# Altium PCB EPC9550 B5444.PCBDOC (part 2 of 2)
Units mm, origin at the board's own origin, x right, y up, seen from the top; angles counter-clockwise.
Board outline 50 x 37 mm, 8 copper layers (Top Layer, Mid-Layer 1, Mid Layer 2 (Gnd), Mid-Layer 3 (Gnd), Mid-Layer 4 (54V), Mid Layer 5 (54V), Mid-Layer 6, Bottom Layer), stack 1.444 mm thick; 107 components, 61 nets, 523 pads, 597 vias.
Unrouted connection lines stored in the file: 17.
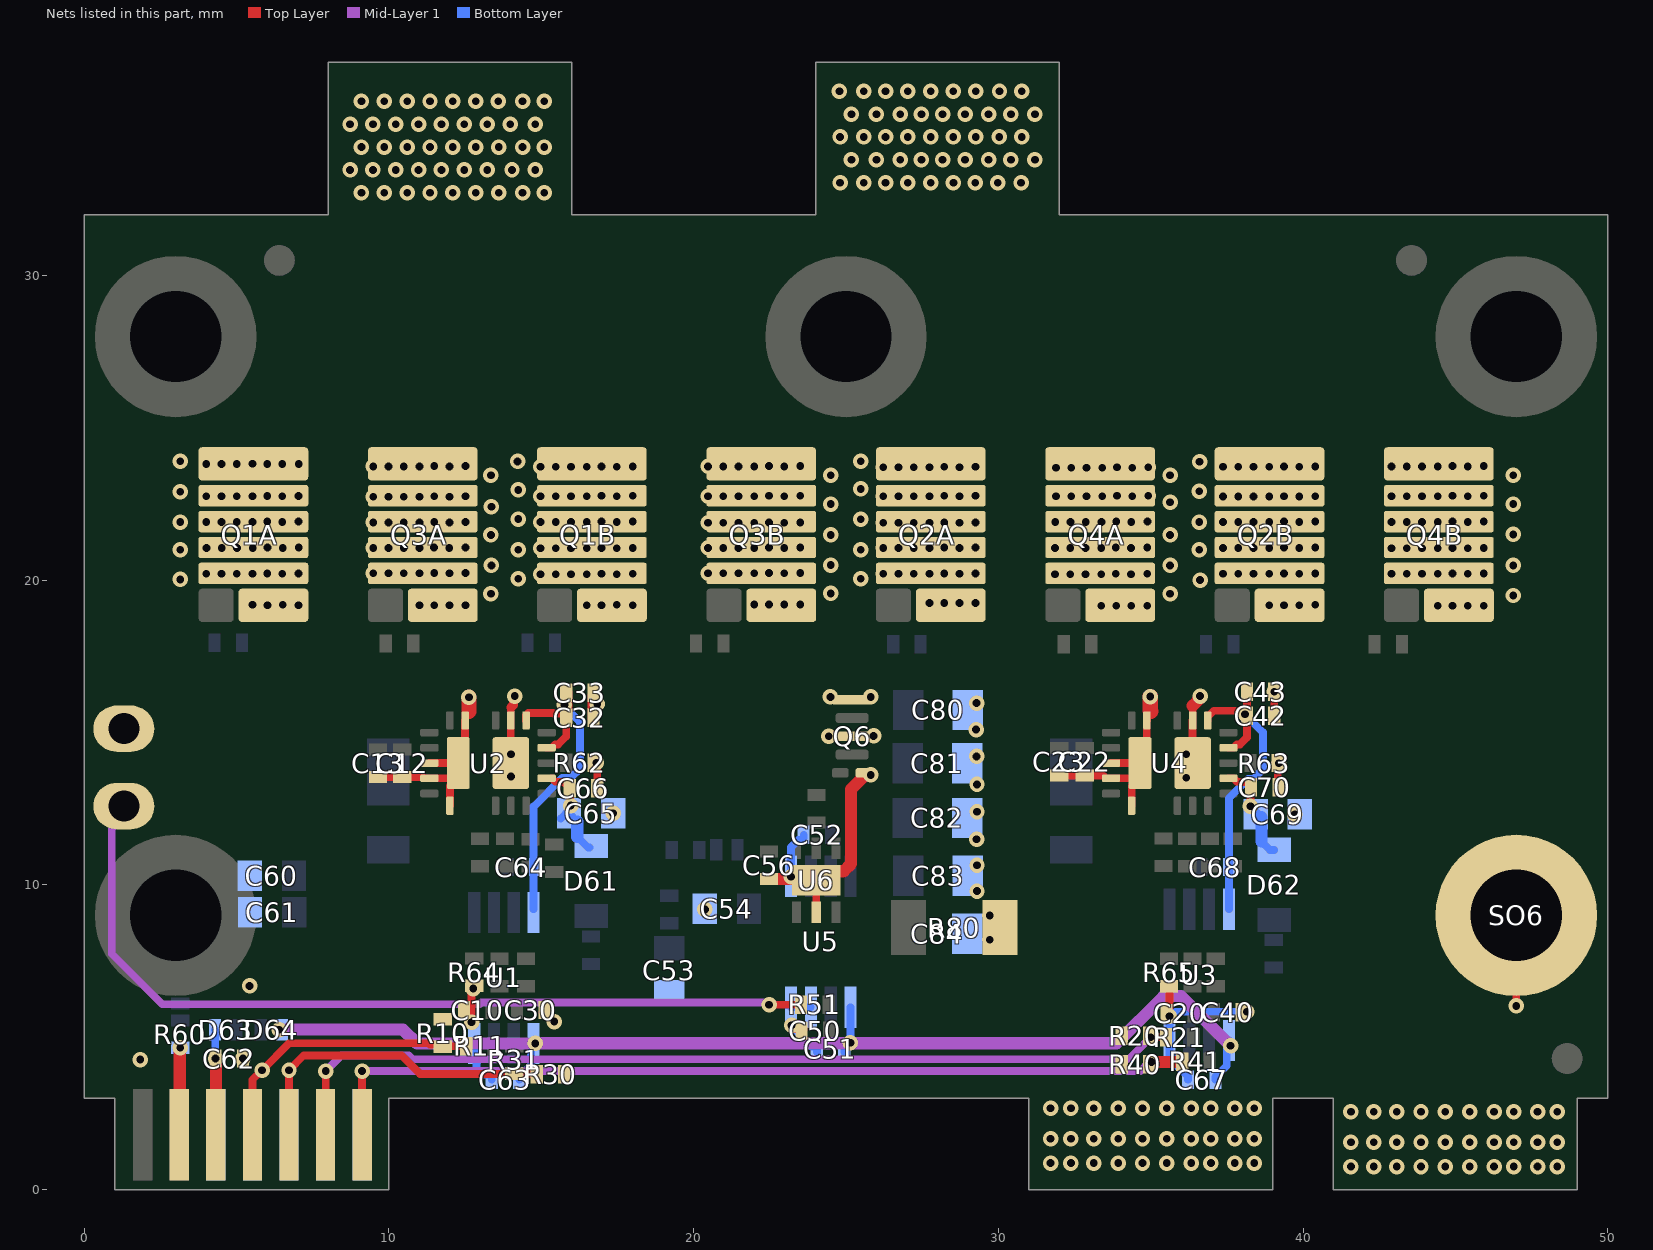
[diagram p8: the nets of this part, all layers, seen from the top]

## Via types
v1: diameter 0.508, hole 0.254, Top Layer to Bottom Layer, tented both sides, 565 vias
v2: diameter 0.508, hole 0.254, Top Layer to Bottom Layer, 32 vias

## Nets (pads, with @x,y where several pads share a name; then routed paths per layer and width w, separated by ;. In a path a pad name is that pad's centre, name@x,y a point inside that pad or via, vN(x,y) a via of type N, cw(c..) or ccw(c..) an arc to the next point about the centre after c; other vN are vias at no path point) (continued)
PRE_54V: C52.2 C54.1 C56.1 Q1A.3 Q1A.5 Q1A.7 Q1B.3 Q1B.5 Q1B.7 Q2A.3 Q2A.5 Q2A.7 Q2B.3 Q2B.5 Q2B.7 Q6.2 Q6.4 Q6.6 U5.5 U6.2 U6.EP | length 8.9
  Top Layer w0.254: v1@23.196,10.2 23.973,10.2 U6.EP@24.023,10.15 ; U6.2@24.023,9.1 U6.EP@24.023,10.15 ; U6.EP@24.057,10.183 U6.EP@24.023,10.15
  Top Layer w0.4: C56.1@22.474,10.2 v1@23.196,10.2 ; U6.EP@24.057,10.183 24.323,10.45 24.926,10.45 25.16,10.684 25.16,13.138 25.632,13.609 v1(25.811,13.609)
  Bottom Layer w0.254: C54.1@20.359,9.225 C54.1@20.368,9.216 ; U5.5@23.196,10.285 23.196,11.237 23.437,11.477 23.537,11.477 23.61,11.55 C52.2@23.61,11.65
  other v1: 31.715,0.87 32.384,0.87 33.132,0.87 33.932,0.87 34.732,0.87 35.532,0.87 36.332,0.87 36.978,0.87 37.757,0.87 38.401,0.87 31.715,1.67 32.384,1.67 33.132,1.67 33.932,1.67 34.732,1.67 35.532,1.67 36.332,1.67 36.978,1.67 37.757,1.67 38.401,1.67 31.715,2.67 32.384,2.67 33.132,2.67 33.932,2.67 34.732,2.67 35.532,2.67 36.332,2.67 36.978,2.67 37.757,2.67 38.401,2.67 20.37,9.195 23.196,10.27 24.438,14.88 25.905,14.89 24.489,16.17 25.811,16.17 36.623,20.007 3.15,20.028 14.242,20.054 25.487,20.054 14.974,20.197 15.474,20.197 15.974,20.197 16.491,20.197 17.474,20.197 4,20.211 4.5,20.211 5,20.211 5.517,20.211 6,20.225 6.5,20.211 7.026,20.225 16.974,20.211 18,20.211 26.224,20.211 26.724,20.211 27.224,20.211 27.741,20.211 28.224,20.225 28.724,20.211 29.25,20.225 37.374,20.211 37.874,20.211 38.374,20.211 38.891,20.211 39.374,20.225 39.874,20.211 40.4,20.225 3.15,21 14.242,21 25.487,21 36.594,21 26.224,21.884 26.724,21.884 27.224,21.884 27.741,21.884 28.224,21.897 28.724,21.884 29.25,21.897 3.15,21.911 4,21.911 4.5,21.911 5,21.911 5.517,21.911 6,21.925 6.5,21.911 7.026,21.925 14.974,21.911 15.474,21.911 15.974,21.911 16.491,21.911 16.974,21.925 17.474,21.911 18,21.925 36.594,21.911 37.374,21.911 37.874,21.911 38.374,21.911 38.891,21.911 39.374,21.925 39.874,21.911 40.4,21.925 25.487,22 14.242,22.01 3.15,22.908 36.594,22.92 14.242,22.966 25.487,22.998 26.224,23.709 26.724,23.709 27.224,23.709 27.741,23.709 28.724,23.709 14.974,23.722 15.474,23.722 15.974,23.722 16.491,23.722 16.974,23.736 17.474,23.722 18,23.736 28.224,23.722 29.25,23.722 37.374,23.722 37.874,23.722 38.374,23.722 38.891,23.722 39.374,23.736 39.874,23.722 40.4,23.736 4,23.816 4.5,23.816 5,23.816 5.517,23.821 6,23.816 6.5,23.816 7.035,23.816 36.604,23.887 3.15,23.906 14.218,23.9 25.487,23.906
PWM_ACL: pad.4@1.3,12.587 R51.1 | length 28.3
  Top Layer w0.254: v1(22.474,6.065) R51.1@23.523,6.065
  Mid-Layer 1 w0.254: pad.4@1.3,12.587 1.3,12.244 0.898,11.841 0.898,7.743 2.557,6.084 12.98,6.084 13.038,6.142 v1@22.474,6.142
S3V: C51.1 C63.1 C67.1 D64.K U1.1 U3.1 U5.1 | length 37.2
  Mid-Layer 1 w0.4: v1(6.392,5.25) 10.461,5.25 10.915,4.796 14.749,4.796 14.756,4.803 25.145,4.803 25.146,4.802 33.878,4.802 35.426,6.35 35.998,6.35 v1(37.624,4.724)
  Bottom Layer w0.254: C63.1@14.273,3.602 14.346,3.675 14.346,3.775 14.673,4.102 14.673,4.723 U1.1@14.746,4.796 v1(14.799,4.796) ; C51.1@24.946,4.518 24.946,4.618 v1(25.146,4.818) U5.1@25.146,5.985 ; C67.1@37.128,3.602 37.128,3.702 37.496,4.07 37.496,4.827 U3.1@37.569,4.9
S5V: C62.1 D63.A pad.2@4.317,1.8 | length 3.5
  Top Layer w0.254: pad.2@4.3,1.817 pad.2@4.317,1.8
  Top Layer w0.4: pad.2@4.3,1.817 4.317,1.835 C62.1@4.317,4.3
  Bottom Layer w0.254: D63.A@4.286,5.25 4.296,5.24 4.296,4.31 v1(4.306,4.3)
S12V: pad.2@3.117,1.8 R60.1 | length 2.9
  Top Layer w0.254: v1(3.15,4.655) v1@3.173,4.677
  Top Layer w0.4: pad.2@3.117,1.8 3.134,1.816 v1@3.134,4.638
SEC_RTN: C32.2 C33.2 C42.2 C43.2 C65.1 C66.2 C69.1 C70.2 C80.2 C81.2 C82.2 C83.2 C84.2 Q3A.2 Q3A.4 Q3A.6 Q3B.2 Q3B.4 Q3B.6 Q4A.2 Q4A.4 Q4A.6 Q4B.2 Q4B.4 Q4B.6 R62.2 R63.2 R80.2 SO6.1 U2.7 U2.20 U4.7 U4.20 | length 11
  Top Layer w0.254: U2.20@14,14 14,15.825 ; v1@14.123,16.198 v1(14.125,16.2) ; C33.2@16.717,16.222 C33.2@16.759,16.264 ; v1(16.8,14.009) 16.833,13.976 C66.2@16.833,13.176 ; U4.20@36.376,14 U4.7@36.376,15.4 36.378,15.402 36.378,15.884 ; v1@36.623,16.129 v1(36.623,16.198) ; C42.2@39.058,15.551 C43.2@39.058,16.341 v1(39.06,16.343) ; C70.2@39.174,13.206 39.174,13.969 v1(39.201,13.996) R63.2@39.201,13.873 ; v1(47,6.027) SO6.1@47,9
  Top Layer w0.3: 14,15.825 14.085,15.91 14.085,16.16 v1@14.123,16.198
  Top Layer w0.4: C32.2@16.717,15.49 C33.2@16.717,16.222 ; 36.378,15.884 v1@36.623,16.129
  Bottom Layer w0.254: v1(29.3,9.8) 29.3,9.827 C83.2@29.373,9.9
  other v1: 41.572,0.756 42.324,0.756 43.073,0.756 43.873,0.756 44.673,0.756 45.473,0.756 46.273,0.756 46.919,0.756 47.698,0.756 48.342,0.756 41.572,1.556 42.324,1.556 43.073,1.556 43.873,1.556 44.673,1.556 45.473,1.556 46.273,1.556 46.919,1.556 47.698,1.556 48.342,1.556 41.572,2.556 42.324,2.556 43.073,2.556 43.873,2.556 44.673,2.556 45.473,2.556 46.273,2.556 46.919,2.556 47.698,2.556 48.342,2.556 29.72,8.2 29.72,9 29.3,10.65 29.285,11.5 39.733,12.315 17.353,12.35 29.3,12.4 29.3,13.3 36.169,13.518 14.002,13.559 29.285,14.219 14.002,14.291 36.169,14.291 29.27,15.1 16.833,15.939 29.285,15.969 33.375,19.161 33.867,19.161 34.367,19.163 34.884,19.161 44.422,19.161 44.905,19.163 45.405,19.161 45.931,19.161 11,19.179 11.483,19.179 11.983,19.179 12.507,19.179 21.991,19.208 22.474,19.208 22.974,19.208 23.5,19.208 46.9,19.5 13.346,19.556 24.496,19.568 35.638,19.556 13.361,20.487 24.496,20.5 35.638,20.487 46.9,20.487 9.481,21.061 9.981,21.061 10.481,21.061 10.998,21.061 11.981,21.061 20.474,21.061 20.974,21.061 21.474,21.061 21.991,21.061 22.974,21.061 31.858,21.061 32.358,21.061 32.858,21.061 33.375,21.061 34.358,21.061 42.905,21.047 43.405,21.047 43.905,21.047 44.422,21.047 44.905,21.061 45.405,21.047 45.931,21.061 11.481,21.075 12.507,21.075 22.474,21.075 23.5,21.075 33.858,21.075 34.884,21.075 13.346,21.487 24.496,21.488 35.638,21.487 46.9,21.506 13.361,22.411 24.496,22.5 46.9,22.5 35.638,22.562 9.483,22.741 9.983,22.741 10.483,22.741 11,22.741 11.983,22.741 11.483,22.754 12.509,22.754 20.474,22.761 20.974,22.761 21.474,22.761 21.991,22.761 22.974,22.761 31.893,22.761 32.393,22.761 32.893,22.761 33.41,22.761 34.393,22.761 42.905,22.761 43.405,22.761 43.905,22.761 44.422,22.761 45.405,22.761 22.474,22.775 23.5,22.775 33.893,22.775 34.919,22.775 44.905,22.775 45.931,22.775 13.346,23.45 24.496,23.45 35.638,23.45 46.9,23.45
SEC_SR1: C12.2 C13.2 Q1A.2 Q1A.4 Q1A.6 Q1B.2 Q1B.4 Q1B.6 Q3A.3 Q3A.5 Q3A.7 Q3B.3 Q3B.5 Q3B.7 U2.9 U2.13 U2.14 U2.16 U2.21 | length 7.5
  Top Layer w0.254: C13.2@9.641,13.546 C12.2@10.431,13.546 11.108,13.546 11.154,13.5 U2.14@11.325,13.5 12.027,13.5 U2.21@12.275,13.748 ; U2.13@11.325,14 U2.21@12.275,14 ; U2.16@12,12.6 12.002,12.602 12.002,13.252 12.275,13.525 U2.21@12.275,13.748 ; 12.625,15.696 12.5,15.571 U2.9@12.5,15.4 12.498,15.398 12.498,14.223 U2.21@12.275,14 ; U2.21@12.275,13.748 U2.21@12.275,14
  Top Layer w0.5: 12.625,15.696 v1(12.625,16.16)
  other v1: 6.009,19.179 7.026,19.179 16.491,19.179 16.974,19.179 18,19.179 5.517,19.193 6.509,19.193 17.474,19.193 9.483,20.227 9.983,20.227 10.483,20.227 11,20.227 11.983,20.227 20.474,20.227 20.974,20.227 21.474,20.227 21.991,20.227 22.974,20.227 11.483,20.241 12.509,20.241 22.474,20.241 23.5,20.241 4.009,21.061 4.509,21.061 5.009,21.061 5.526,21.061 6.509,21.061 14.974,21.047 15.474,21.047 15.974,21.047 16.491,21.047 16.974,21.061 17.474,21.047 18,21.061 6.009,21.075 7.035,21.075 9.483,21.897 9.983,21.897 10.483,21.897 11,21.897 11.983,21.897 20.474,21.884 20.974,21.884 21.474,21.884 21.991,21.884 22.474,21.897 22.974,21.884 23.5,21.897 11.483,21.911 12.509,21.911 4,22.754 4.5,22.754 5,22.754 5.517,22.754 6,22.768 6.5,22.754 7.026,22.768 14.974,22.761 15.474,22.761 15.974,22.761 16.491,22.761 17.474,22.761 16.974,22.775 18,22.775 9.483,23.736 9.983,23.736 10.483,23.736 11,23.736 11.983,23.736 20.474,23.736 20.974,23.736 21.474,23.736 21.991,23.736 22.974,23.736 11.483,23.75 12.509,23.75 22.474,23.75 23.5,23.75 13.606,32.719 14.383,32.719 15.1,32.719 14.037,33.469 14.8,33.469 13.606,34.219 14.383,34.219 15.1,34.219 13.981,34.969 14.8,34.969 13.585,35.719 14.383,35.719 15.1,35.719
  other v2: 9.096,32.719 9.846,32.719 10.596,32.719 11.346,32.719 12.096,32.719 12.846,32.719 8.721,33.469 9.471,33.469 10.221,33.469 10.971,33.469 11.721,33.469 12.471,33.469 13.221,33.469 9.096,34.219 9.846,34.219 10.596,34.219 11.346,34.219 12.096,34.219 12.846,34.219 8.721,34.969 9.471,34.969 10.221,34.969 10.971,34.969 11.721,34.969 12.471,34.969 13.221,34.969 9.096,35.719 9.846,35.719 10.596,35.719 11.346,35.719 12.096,35.719 12.846,35.719
SEC_SR2: C22.2 C23.2 Q2A.2 Q2A.4 Q2A.6 Q2B.2 Q2B.4 Q2B.6 Q4A.3 Q4A.5 Q4A.7 Q4B.3 Q4B.5 Q4B.7 U4.9 U4.13 U4.14 U4.16 U4.21 | length 7.6
  Top Layer w0.254: C23.2@32,13.595 C22.2@32.84,13.595 33.435,13.595 33.53,13.5 U4.14@33.701,13.5 34.403,13.5 U4.21@34.651,13.748 ; U4.13@33.701,14 U4.21@34.651,14 ; U4.16@34.376,12.6 34.378,12.602 34.378,13.252 34.651,13.525 U4.21@34.651,13.748 ; 35.01,15.705 34.876,15.571 U4.9@34.876,15.4 34.874,15.398 34.874,14.223 U4.21@34.651,14 ; U4.21@34.651,13.748 U4.21@34.651,14
  Top Layer w0.5: v1(34.986,16.183) 34.988,16.182 34.988,15.726 35.01,15.705
  other v1: 38.891,19.179 39.374,19.179 39.874,19.179 40.4,19.193 27.741,19.256 28.224,19.256 28.724,19.256 29.25,19.256 31.858,20.197 32.358,20.197 32.858,20.197 33.375,20.197 34.358,20.197 33.858,20.211 34.884,20.211 42.905,20.211 43.405,20.211 43.905,20.211 44.422,20.211 44.905,20.225 45.405,20.211 45.931,20.225 26.224,21.061 26.724,21.061 27.224,21.061 27.741,21.061 28.724,21.061 37.374,21.061 37.874,21.061 38.374,21.061 38.891,21.061 39.874,21.061 28.224,21.075 29.25,21.075 39.374,21.075 40.4,21.075 31.867,21.911 32.367,21.911 32.867,21.911 33.384,21.911 33.867,21.925 34.367,21.911 34.893,21.925 42.905,21.911 43.405,21.911 43.905,21.911 44.422,21.911 44.905,21.925 45.405,21.911 45.931,21.925 26.224,22.761 26.724,22.761 27.224,22.761 27.741,22.761 28.724,22.761 37.374,22.747 37.874,22.747 38.374,22.747 38.891,22.747 39.374,22.761 39.874,22.747 40.4,22.761 28.224,22.775 29.25,22.775 31.893,23.695 32.393,23.695 32.893,23.695 33.41,23.695 33.893,23.709 34.393,23.695 34.919,23.709 42.905,23.736 43.405,23.736 43.905,23.736 44.422,23.736 45.405,23.736 44.905,23.75 45.931,23.75 24.805,33.05 25.581,33.05 26.298,33.05 27.031,33.05 27.778,33.05 28.527,33.05 29.245,33.05 29.977,33.05 30.744,33.05 25.179,33.8 25.998,33.8 26.78,33.8 27.476,33.8 28.169,33.8 28.908,33.8 29.678,33.8 30.413,33.8 31.2,33.8 24.805,34.55 25.581,34.55 26.298,34.55 27.031,34.55 27.778,34.55 28.521,34.55 29.262,34.55 30.026,34.55 30.765,34.55 25.179,35.3 25.998,35.3 26.78,35.3 27.476,35.3 28.169,35.3 28.908,35.3 29.678,35.3 30.413,35.3 31.2,35.3 24.784,36.05 25.581,36.05 26.298,36.05 27.031,36.05 27.778,36.05 28.521,36.05 29.262,36.05 30.039,36.05 30.765,36.05
SGND: C10.2 C20.2 C30.2 C40.2 C50.2 C51.2 C53.1 C60.1 C61.2 C62.2 C63.2 C67.2 pad.2@4.317,1.8 pad.2@5.517,1.8 pad.2@6.717,1.8 pad.2@7.918,1.8 pad.2@9.118,1.8 pad.4@1.3,15.127 R10.2 R20.2 R30.2 R40.2 R64.1 R65.1 U1.4 U3.4 U5.3 U5.4 | length 16.8
  Top Layer w0.254: v1(12.709,5.492) 12.709,6.542 v1(12.766,6.6) ; C30.2@15.03,5.819 C30.2@15.103,5.892 ; v1(23.213,5.392) v1@23.262,5.343 ; C50.2@23.538,5.218 C50.2@23.538,5.27 ; R65.1@35.602,6.676 35.602,6.615 35.614,6.603 C20.2@35.614,5.99
  Top Layer w0.4: v1@23.262,5.343 23.465,5.343 C50.2@23.538,5.27
  Bottom Layer w0.254: pad.2@4.317,1.8 pad.2@4.317,2.982 ; pad.2@5.517,1.8 pad.2@5.517,2.982 ; pad.2@6.717,1.8 pad.2@6.717,2.982 ; pad.2@7.918,1.8 pad.2@7.918,2.982 ; pad.2@9.118,1.8 pad.2@9.118,2.982 ; U1.4@12.796,4.9 12.869,4.827 12.869,4.099 12.869,3.924 13.018,3.775 13.3,3.775 13.373,3.702 C63.2@13.373,3.602 ; U5.4@23.196,5.985 U5.3@23.846,5.985 ; U5.4@23.254,5.393 23.254,5.31 23.873,4.691 23.973,4.691 24.046,4.618 C51.2@24.046,4.518 ; C67.2@36.228,3.602 36.228,3.702 35.976,3.955 35.968,3.955 35.807,4.116 35.807,4.237 35.619,4.425 U3.4@35.619,4.9 35.617,4.902 35.617,5.691 v1(35.614,5.694) 35.683,5.694 35.827,5.837 v1(38.162,5.837)
  other v1: 1.839,4.27 5.206,4.3 15.42,5.515 5.425,6.684
SR_HSDRV1: pad.2@5.517,1.8 R10.1 R11.1 | length 9.6
  Top Layer w0.254: pad.2@5.684,1.966 pad.2@5.517,1.8 5.517,3.6 v1(5.835,3.917) 6.719,4.802 11.303,4.802 11.342,4.763 11.71,4.763 11.768,4.705 R11.1@12.538,4.705
SR_HSDRV2: pad.2@7.918,1.8 R20.1 R21.1 | length 30.3
  Top Layer w0.254: pad.2@7.918,1.8 7.925,1.807 v1(7.925,3.889) ; v1(35.001,5.005) R21.1@35.5,5.005
  Top Layer w0.4: R21.1@35.5,5.005 R21.1@35.5,5.105
  Mid-Layer 1 w0.254: v1@7.93,3.894 8.441,4.405 10.652,4.405 10.777,4.28 34.276,4.28 v1(35.001,5.005)
SR_LSDRV1: pad.2@6.717,1.8 R30.1 R31.1 | length 10.7
  Top Layer w0.254: pad.2@6.717,1.8 v1(6.717,3.917) 7.205,4.405 10.412,4.405 11.019,3.797 R31.1@14.11,3.797 ; R31.1@14.11,3.805 14.118,3.797 14.845,3.797 R30.1@14.853,3.789
SR_LSDRV2: pad.2@9.118,1.8 R40.1 R41.1 | length 29.1
  Top Layer w0.254: pad.2@9.118,1.8 v1(9.118,3.889)
  Top Layer w0.4: v1(35.027,4.189) 35.03,4.192 36.034,4.192 R41.1@36.034,4.195
  Mid-Layer 1 w0.254: v1(9.118,3.889) 34.659,3.889 34.959,4.189 v1(35.027,4.189)
U1-5V: C32.1 C33.1 C64.1 U1.8 U2.4 U2.6 | length 11.8
  Top Layer w0.254: U2.6@14.5,15.4 14.5,15.571 14.572,15.643 15.391,15.643 15.41,15.624 C32.1@15.744,15.624 ; U2.4@15.175,14.5 15.346,14.5 15.459,14.613 15.554,14.613 15.817,14.876 C32.1@15.817,15.49 C32.1@15.817,15.551 ; v1(15.76,15.91) 15.788,15.939 15.788,16.277 C33.1@15.817,16.305
  Top Layer w0.4: C32.1@15.817,15.551 C33.1@15.817,16.305
  Bottom Layer w0.254: U1.8@14.746,9.2 14.746,12.572 15.693,13.518 15.97,13.518 16.272,13.821 16.272,15.345 15.76,15.856 v1(15.76,15.91)
U1-12V: C65.2 C66.1 D61.K U2.2 | length 3.2
  Top Layer w0.254: U2.2@15.348,13.498 15.459,13.387 15.722,13.387 15.76,13.349 15.86,13.349 15.933,13.276 C66.1@15.933,13.176 15.95,13.159 15.95,12.622 v1(15.968,12.605)
  Bottom Layer w0.254: C65.2@15.635,12.177 C65.2@15.935,12.477 ; C65.2@15.908,12.35 C65.2@16.181,12.077 ; D61.K@16.181,11.582 16.537,11.225 D61.K@16.579,11.225
  Bottom Layer w0.4: D61.K@16.181,11.582 C65.2@16.181,12.077
U2-5V: C42.1 C43.1 C68.1 U3.8 U4.4 U4.6 | length 11
  Top Layer w0.254: U4.6@36.876,15.4 36.876,15.571 36.878,15.573 36.924,15.573 37.071,15.72 38.024,15.72 38.1,15.645 v1(38.1,15.6) ; U4.4@37.551,14.5 37.722,14.5 37.835,14.613 37.93,14.613 38.158,14.841 C42.1@38.158,15.551 38.158,15.57 C43.1@38.158,16.341
  Bottom Layer w0.254: U3.8@37.569,9.2 37.569,12.848 38.206,13.486 38.383,13.486 38.685,13.788 38.685,15.015 v1(38.1,15.6)
U2-12V: C69.2 C70.1 D62.K U4.2 | length 3.1
  Top Layer w0.254: U4.2@37.551,13.5 37.722,13.5 37.835,13.387 37.93,13.387 37.938,13.379 38.201,13.379 38.294,13.286 C70.1@38.294,13.206 ; v1(38.274,12.585) 38.274,12.885
  Bottom Layer w0.254: v1(38.274,12.585) C69.2@38.637,12.222 ; D62.K@38.637,11.423 38.91,11.15 D62.K@39.06,11.15
  Bottom Layer w0.4: D62.K@38.637,11.423 C69.2@38.637,12.222
pads on no net: FD1.0 FD2.0 FD3.0 Q1A. Q1B. Q2A. Q2B. Q3A. Q3B. Q4A. Q4B. Q6. SO1.1 SO2.1 SO3.1 SO4.1 U2.0 U2.1 U2.11 U2.15 U4.0 U4.1 U4.11 U4.15 U5.6

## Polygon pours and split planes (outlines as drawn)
SEC_SR2 on Mid-Layer 1 "NONET_L-01_P-001" (solid, pour order 125): 24.3,32.267 24.3,36.75 32.318,36.75 32.318,31.898 49.998,31.898 50,32 50,18.65 24.3,18.65
SGND on Mid-Layer 1 "NONET_L-01_P-001" (solid, pour order 114): 3.657,11.87 5.325,10.202 5.325,7.7 12.264,7.7 12.264,6.876 38.522,6.876 38.522,3.196 0.063,3.196 0.063,17.306 3.053,17.306 3.657,16.702
SEC_RTN on Mid-Layer 1 "NONET_L-01_P-001" (solid, pour order 148): 27.966,16.806 27.966,7.297 12.962,7.297 12.941,7.318 12.941,8.132 5.546,8.132 5.546,16.806
SEC_RTN on Mid-Layer 1 "NONET_L-01_P-001" (solid, pour order 132): 39.296,7.346 39.363,7.279 39.363,3 50,3 50,5.573 44.453,5.573 44.35,5.676 44.396,5.722 44.396,11.384 50,11.384 50,18.253 44.261,18.309 43.997,18.045 43.997,17.339 43.684,17.026 30.473,17.026 30.473,7.359 38.891,7.359 38.904,7.346
SEC_RTN on Mid-Layer 1 "NONET_L-01_P-001" (solid, pour order 116): 15.451,16.502 14.88,16.502 14.295,15.921 14.295,15.104 14.242,15.05 13.133,15.037 13.121,16.721 13.777,17.377 14.967,17.377 15.051,17.461 15.051,17.8 15.896,17.8 15.896,16.947
SEC_RTN on Mid-Layer 1 "NONET_L-01_P-001" (solid, pour order 115): 36.422,15.05 36.604,15.233 36.614,15.766 38.169,16.977 38.169,17.798 36.867,17.798 36.867,17.417 36.786,17.336 35.994,17.339 35.426,16.771 35.426,15.05
SEC_SR1 on Mid-Layer 1 "NONET_L-01_P-001" (solid, pour order 124): 8,31.962 8,37.252 15.999,37.08 15.999,31.999 24.05,32.036 24.05,18.584 0.05,18.584 0.05,31.925
SEC_RTN on Mid-Layer 1 "NONET_L-01_P-001" (solid, pour order 113): 44.85,19.737 44.85,18.621 43.942,18.621 43.55,18.23 43.55,17.563 31.55,17.563 31.55,19.625 31.633,19.708 32.642,19.708 33.75,19.737 33.75,18.65 32.933,18.65 32.685,18.402 32.685,18.25 42.358,18.25 42.65,18.542 42.65,19.528 42.859,19.737
SEC_RTN on Mid-Layer 1 "NONET_L-01_P-001" (solid, pour order 112): 21.833,19.743 22.3,19.743 22.3,18.584 21.833,18.584 21.283,18.034 21.283,17.563 9.413,17.563 9.287,17.436 9.287,19.436 9.593,19.743 11.343,19.743 11.343,18.643 10.481,18.643 10.481,18.385 10.483,18.383 10.483,18.25 20.283,18.25 20.45,18.417 20.45,19.666 20.527,19.743
SEC_SR2 on Mid-Layer 6 "NONET_L-01_P-001" (solid, pour order 126): 24.3,32 24.3,36.69 32.393,36.69 32.393,31.838 49.998,31.838 50,31.94 50,18.6 24.3,18.6
SEC_RTN on Mid-Layer 6 "NONET_L-01_P-001" (solid, pour order 133): 0,16.842 0.042,16.8 3.371,16.8 3.371,11.645 3.352,11.627 3.38,11.599 5.78,11.599 5.78,10.84 5.814,10.805 7.255,10.805 7.255,8.589 7.41,8.435 20.279,8.435 21.022,7.692 26.242,7.692 44.96,7.507 44.96,11.055 49.998,11.055 50,11.053 49.964,11.017 49.964,7.2 49.964,3 0,3
SEC_RTN on Mid-Layer 6 "NONET_L-01_P-001" (solid, pour order 147): 3.78,16.683 3.78,12.049 6.211,12.049 6.211,11.219 7.705,11.219 7.705,8.8 20.571,8.8 21.302,8.07 44.516,8.07 44.5,8.086 44.5,11.5 49.993,11.5 50,11.507 50,16.683
SEC_SR2 on Mid-Layer 6 "NONET_L-01_P-001" (solid, pour order 123): 32.698,17.183 32.865,17.016 35.362,17.016 35.362,15.289 33.078,15.289 33.078,12.605 31.3,12.605 31.3,17.64 32.698,17.64
SEC_SR1 on Mid-Layer 6 "NONET_L-01_P-001" (solid, pour order 127): 8,31.752 8,37.043 15.999,36.87 15.999,31.789 24.062,31.827 24.062,18.6 0.062,18.6 0.062,31.715
SEC_SR1 on Mid-Layer 6 "NONET_L-01_P-001" (solid, pour order 122): 10.742,12.587 10.742,15.245 12.923,15.245 12.923,17.016 11.234,17.016 10.9,17.35 10.9,17.65 10.893,17.643 8.846,17.643 8.846,12.587
SEC_SR2 on Mid-Layer 6 "NONET_L-01_P-001" (solid, pour order 110): 28.224,19.7 28.224,18.659 28.219,18.663 27.315,18.665 27.116,18.466 27.116,18.35 27.266,18.2 37.149,18.2 37.416,18.467 37.416,19.453 37.663,19.7 39.2,19.7 39.2,18.667 38.509,18.659 38.166,18.316 38.166,17.53 26.296,17.53 26.266,17.5 26.266,19.5 26.466,19.7
SEC_SR1 on Mid-Layer 6 "NONET_L-01_P-001" (solid, pour order 109): 16.416,19.7 16.974,19.7 16.974,18.667 16.167,18.667 16.141,18.641 15.866,18.366 15.866,17.63 3.996,17.63 3.966,17.6 3.966,19.293 4.373,19.7 5.316,19.7 5.95,19.7 5.95,18.641 5.933,18.659 5.021,18.654 4.816,18.45 5.016,18.25 14.799,18.25 15.116,18.567 15.116,19.266 15.55,19.7
SEC_RTN on Top Layer "NONET_L-01_P-001" (solid, pour order 152): 27.9,17.137 30.8,17.137 30.8,7.281 28,7.281 28,17.037
SEC_RTN on Top Layer "NONET_L-01_P-001" (solid, pour order 150): 19.679,8.6 20.503,7.776 25.889,7.776 25.916,7.749 25.925,7.758 25.925,17.137 3.117,17.137 3.117,12.049 4.469,12.049 7.918,8.6
NetC80_1 on Top Layer "NONET_L-01_P-001" (solid, pour order 142): 24.238,16.487 27.612,16.487 27.612,13.346 24.238,13.346
SEC_RTN on Top Layer "NONET_L-01_P-001" (solid, pour order 131): 50.135,11.852 44.14,11.852 44.14,5.518 50.135,5.518 50.135,3.125 40.135,3.125 40.135,7.281 31.1,7.281 31.1,17.137 43.828,17.137 50.135,17.137
SEC_SR1 on Top Layer "NONET_L-01_P-001" (solid, pour order 68): 11.058,20.096 9.981,20.096 9.979,20.094 9.979,18.633 5.517,18.633 5.517,25 11.058,25
SEC_SR1 on Top Layer "NONET_L-01_P-001" (solid, pour order 69): 22.168,20.007 21.093,20.007 21.089,20.003 21.091,20.001 21.091,18.633 16.66,18.633 16.66,25.2 22.168,25.2
SEC_RTN on Top Layer "NONET_L-01_P-001" (solid, pour order 70): 11.11,19.269 11.746,18.633 13.672,18.633 13.672,24.367 11.11,24.367
PRE_54V on Top Layer "NONET_L-01_P-001" (solid, pour order 71): 16.598,20.133 16.383,19.918 15.531,19.918 15.531,18.633 13.807,18.633 13.807,24.367 16.598,24.367
SEC_RTN on Top Layer "NONET_L-01_P-001" (solid, pour order 72): 22.22,18.633 24.884,18.633 24.884,24.367 22.22,24.367
PRE_54V on Top Layer "NONET_L-01_P-001" (solid, pour order 73): 5.462,20.288 5.092,19.918 4.421,19.918 4.421,19.208 3.845,18.633 0.1,18.633 0.1,24.353 5.462,24.353
SEC_SR2 on Top Layer "NONET_L-01_P-001" (solid, pour order 83): 32.25,20.317 32.25,18.633 27.78,18.633 27.78,24.75 33.349,24.75 33.349,20.317
SEC_RTN on Top Layer "NONET_L-01_P-001" (solid, pour order 85): 33.391,18.633 35.95,18.633 35.95,24.367 33.391,24.367
PRE_54V on Top Layer "NONET_L-01_P-001" (solid, pour order 86): 38.75,20 38.744,19.994 38.744,18.633 36.1,18.633 36.1,24.367 38.75,24.367
SEC_RTN on Top Layer "NONET_L-01_P-001" (solid, pour order 87): 44.46,18.65 50.13,18.65 50.13,24.353 44.46,24.353
PRE_54V on Top Layer "NONET_L-01_P-001" (solid, pour order 88): 27.694,20.241 27.612,20.322 26.713,20.322 26.713,18.65 25.097,18.65 25.097,24.367 27.694,24.366
SEC_SR2 on Top Layer "NONET_L-01_P-001" (solid, pour order 111): 44.376,20.298 43.389,20.298 43.389,18.65 38.906,18.65 38.906,19.973 38.906,24.823 44.376,24.823
SGND on Top Layer "NONET_L-01_P-001" (solid, pour order 117): 12.203,6.888 12.203,7.776 0,7.776 0,3.208 38.522,3.125 38.522,6.888
SEC_SR2 on Top Layer "NONET_L-01_P-001" (solid, pour order 89): 24,32 24,37 32,37 32,32 50,32 50,24.1 24,24.1
PRE_54V on Top Layer "NONET_L-01_P-001" (solid, pour order 80): 31.267,3 31.267,0.267 38.733,0.267 38.733,3
SEC_RTN on Top Layer "NONET_L-01_P-001" (solid, pour order 79): 41.267,3 41.267,0.267 48.733,0.267 48.733,3
SEC_SR1 on Top Layer "NONET_L-01_P-001" (solid, pour order 60): 8,31.968 8,37 16,37 16,31.991 24,32.028 24,23.736 0,23.736 0,31.93
SEC_RTN on Bottom Layer "NONET_L-01_P-001" (solid, pour order 151): 50.088,11.855 44.092,11.855 44.092,5.521 50.088,5.521 50.088,3.128 40.088,3.128 40.088,7.284 30.753,7.284 30.753,17.14 43.78,17.14 50.088,17.14
SEC_RTN on Bottom Layer "NONET_L-01_P-001" (solid, pour order 149): 3.802,17.1 3.802,11.984 6.292,11.984 6.292,8.594 21.492,8.594 25.913,8.594 25.913,17.1
SGND on Bottom Layer "NONET_L-01_P-001" (solid, pour order 118): 5.784,11.582 5.748,11.618 3.409,11.618 3.409,16.782 3.435,16.809 -0.049,16.809 -0.049,3.111 39.692,3.111 39.692,6.908 27.919,6.908 27.919,6.972 5.784,6.972
SEC_RTN on Bottom Layer "NONET_L-01_P-001" (solid, pour order 136): 29.979,10.475 29.979,7.74 28.497,7.74 28.497,16.406 29.955,16.406 29.979,16.43
NetC80_1 on Bottom Layer "NONET_L-01_P-001" (solid, pour order 146): 26.27,7.74 28.146,7.74 28.146,16.406 26.27,16.406
SEC_RTN on Bottom Layer "NONET_L-01_P-001" (solid, pour order 64): 35.3,24.189 35.3,23.372 33.32,23.372 33.3,23.399 33.3,19.722 32.903,19.722 32.84,19.659 32.84,18.65 35.944,18.65 35.944,24.189
SEC_SR2 on Bottom Layer "NONET_L-01_P-001" (solid, pour order 62): 27.75,19.736 27.736,19.722 27.3,19.722 27.3,18.65 32.251,18.65 32.251,20.316 33.2,20.316 33.2,24.78 27.75,24.78
SEC_SR2 on Bottom Layer "NONET_L-01_P-001" (solid, pour order 63): 38.88,19.691 38.853,19.718 38.46,19.718 38.46,18.65 43.363,18.65 43.363,20.324 44.35,20.324 44.35,24.85 38.88,24.85 38.88,20
PRE_54V on Bottom Layer "NONET_L-01_P-001" (solid, pour order 65): 38.744,20.316 37.803,20.316 37.803,18.65 36.079,18.65 36.079,24.214 38.744,24.214
SEC_RTN on Bottom Layer "NONET_L-01_P-001" (solid, pour order 66): 44.45,19.718 43.942,19.718 43.942,18.65 50.11,18.65 50.11,24.167 44.45,24.167
PRE_54V on Bottom Layer "NONET_L-01_P-001" (solid, pour order 67): 27.596,20.285 26.693,20.285 26.693,18.65 25.1,18.65 25.1,24.203 27.596,24.203
SEC_SR1 on Bottom Layer "NONET_L-01_P-001" (solid, pour order 90): 5.628,22.815 5.633,22.81 6.259,22.81 6.259,20.19 5.009,20.19 5.009,18.65 9.951,18.65 9.951,20.316 11.031,20.316 11.031,24.997 5.628,24.997
SEC_SR1 on Bottom Layer "NONET_L-01_P-001" (solid, pour order 91): 16.737,19.733 16.734,19.736 16.173,19.736 16.173,18.65 21.063,18.65 21.063,20.316 22.141,20.316 22.141,25.197 16.737,25.197
SEC_RTN on Bottom Layer "NONET_L-01_P-001" (solid, pour order 92): 11.137,19.733 11.132,19.729 10.647,19.729 10.647,18.655 10.652,18.65 13.671,18.65 13.671,24.186 11.145,24.186 11.145,20.004 11.137,20.004
PRE_54V on Bottom Layer "NONET_L-01_P-001" (solid, pour order 93): 16.633,20.316 15.503,20.316 15.503,18.65 13.827,18.65 13.827,24.189 16.633,24.189
PRE_54V on Bottom Layer "NONET_L-01_P-001" (solid, pour order 95): 5.482,19.869 4.089,19.869 4.078,19.88 4.078,18.65 0.073,18.65 0.073,24.186 5.482,24.186
SEC_RTN on Bottom Layer "NONET_L-01_P-001" (solid, pour order 108): 22.25,19.736 21.797,19.736 21.75,19.689 21.75,18.65 24.893,18.65 24.893,24.203 22.25,24.203
SEC_SR2 on Bottom Layer "NONET_L-01_P-001" (solid, pour order 61): 24.201,23.906 23.876,37 31.95,37 31.95,32 50,32 50,23.906
SEC_SR1 on Bottom Layer "NONET_L-01_P-001" (solid, pour order 96): 8,32.3 8,37 16,37 16,32 24,32 24,24.167 0,24.167 0,32.3
PRE_54V on Bottom Layer "NONET_L-01_P-001" (solid, pour order 81): 31.2,3 31.2,0.267 38.8,0.267 38.8,3
SEC_RTN on Bottom Layer "NONET_L-01_P-001" (solid, pour order 82): 41.246,3 41.246,0.267 48.712,0.267 48.712,3
no net on Top Solder "NONET_L-01_P-001" (solid): 8,37 8,32 16,32 16,37
no net on Top Solder "NONET_L-01_P-001" (solid): 24,37 24,32 32,32 32,37
no net on Top Solder "NONET_L-01_P-001" (solid): 31,3 31,0 39,0 39,3 31,3
no net on Top Solder "NONET_L-01_P-001" (solid): 41,3 41,0 49,0 49,3 41,3
PRE_54V on Mid-Layer 4 (54V) "NONET_L-01_P-001" (solid, pour order 121): 31,3 31,0 39.374,0 39.374,3 49.95,3 49.95,31.921 0,31.921 0,3
SEC_RTN on Mid Layer 2 (Gnd) "NONET_L-01_P-001" (solid, pour order 141): 41,3.1 41,0 49,0 49,3.1
SEC_RTN on Mid Layer 2 (Gnd) "NONET_L-01_P-001" (solid, pour order 129): 0,32 50,32 50,3 0,3
no net on Bottom Solder "NONET_L-01_P-001" (solid): 41,3 41,0 49,0 49,3 41,3
no net on Bottom Solder "NONET_L-01_P-001" (solid): 31,3 31,0 39,0 39,3 31,3
no net on Bottom Solder "NONET_L-01_P-001" (solid): 8,37 8,32 16,32 16,37
no net on Bottom Solder "NONET_L-01_P-001" (solid): 24,37 24,32 32,32 32,37
SEC_RTN on Mid-Layer 3 (Gnd) "NONET_L-01_P-001" (solid, pour order 120): 41,3 41,0 49,0 49,3 50.125,3 50.125,32 -0.025,32 -0.025,3
PRE_54V on Mid Layer 5 (54V) "NONET_L-01_P-001" (solid, pour order 130): 31,3 31,0 39.374,0 39.374,3 50.027,3 50.027,31.921 0.077,31.921 0.077,3

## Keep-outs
Mid-Layer 6:
  lines w0.01: 26.449,7.835 26.514,7.77 30.7,7.77 30.7,12.939 30.777,13.017 31.154,13.017 ; 26.449,7.857 26.449,17.094
Mid-Layer 3 (Gnd):
  circle w0.1: c36.623,16.198 r0.5
  circle w0.1: c14.125,16.2 r0.5
Mid Layer 2 (Gnd):
  circle w0.1: c36.623,16.198 r0.5
  lines w0.1: 14.622,16.25 ccw(c14.125,16.2) 14.625,16.2
Bottom Layer:
  circle w0.1: c14.125,16.2 r0.5
  lines w0.1: 37.12,16.248 ccw(c36.623,16.198) 37.123,16.198
Keep-Out Layer:
  lines w0.254: 49,3 50,3 50,32 32,32 32,37 24,37 24,32 16,32 16,37 8,37 8,32 0,32 0,3 1,3 1,0 10,0 10,3 30.996,3 30.996,0 39,0 39,3 41,3 41,0 49,0 49,3 ; 49,3 49,3

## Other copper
Bottom Layer:
  rectangle net SEC_SR2: 31.552,23.475 35.095,24.175
  rectangle net PRE_54V: 26.043,19.882 29.585,20.582
  rectangle net PRE_54V: 25.987,23.489 29.53,24.189
  rectangle net SEC_SR2: 25.948,22.429 29.49,23.129
  rectangle net PRE_54V: 26.015,21.582 29.557,22.282
  rectangle net SEC_RTN: 31.512,22.415 35.055,23.115
  rectangle net SEC_SR2: 31.579,21.568 35.122,22.268
  rectangle net SEC_RTN: 31.512,20.711 35.055,21.411
  rectangle net SEC_SR2: 31.608,19.868 35.15,20.568
  rectangle net SEC_SR2: 25.948,20.725 29.49,21.425
  rectangle net PRE_54V: 3.83,19.88 7.372,20.58
  rectangle net SEC_RTN: 9.319,20.722 12.861,21.422
  rectangle net SEC_SR1: 9.359,23.486 12.901,24.186
  rectangle net PRE_54V: 37.141,23.503 40.684,24.203
  rectangle net SEC_SR2: 37.101,20.738 40.644,21.438
  rectangle net SEC_SR2: 37.101,22.443 40.644,23.143
  rectangle net PRE_54V: 37.168,21.595 40.711,22.295
  rectangle net SEC_SR1: 3.735,20.722 7.277,21.422
  rectangle net SEC_SR1: 20.517,19.882 24.06,20.582
  rectangle net SEC_SR2: 42.743,19.864 46.285,20.564
  rectangle net SEC_RTN: 42.648,20.707 46.19,21.407
  rectangle net PRE_54V: 37.197,19.896 40.739,20.596
  rectangle net PRE_54V: 3.774,23.486 7.317,24.186
  rectangle net PRE_54V: 3.802,21.579 7.344,22.279
  rectangle net SEC_SR1: 3.735,22.427 7.277,23.127
  rectangle net SEC_SR1: 20.489,21.582 24.032,22.282
  rectangle net SEC_SR1: 20.462,23.489 24.004,24.189
  rectangle net PRE_54V: 14.884,23.486 18.427,24.186
  rectangle net SEC_SR2: 42.715,21.564 46.257,22.264
  rectangle net SEC_RTN: 42.648,22.411 46.19,23.111
  rectangle net SEC_SR2: 42.687,23.471 46.23,24.171
  rectangle net SEC_RTN: 20.422,22.429 23.965,23.129
  rectangle net PRE_54V: 14.94,19.88 18.482,20.58
  rectangle net SEC_SR1: 14.845,20.722 18.387,21.422
  rectangle net SEC_RTN: 9.319,22.427 12.861,23.127
  rectangle net SEC_SR1: 9.386,21.579 12.928,22.279
  rectangle net SEC_SR1: 9.414,19.88 12.957,20.58
  rectangle net SEC_RTN: 20.422,20.725 23.965,21.425
  rectangle net PRE_54V: 14.912,21.579 18.454,22.279
  rectangle net SEC_SR1: 14.845,22.427 18.387,23.127
  rectangle net SGND: 3.735,3.1 9.67,3.5

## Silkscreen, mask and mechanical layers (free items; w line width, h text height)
Top Overlay:
  text "EPC9550  B5444   HPE AP-2.1  FETS: EPC2302 + AC" at 49.124,12.145 h1 r90
Bottom Overlay:
  text "EPC9550  B5444   HPE AP-2.1  FETS: EPC2302 + AC" at 49.19,24.433 h1 r90
  text "SGND" at 2.8,16.211 h1
  text "PWM ACL" at 4.372,10.874 h1
Mechanical 1:
  lines w0.25: 0,32 0,3 ; 0,3 0,3
  lines w0.254: 0,3 1,3 1,0 9.994,0 9.994,3 31.128,3 31.128,0 39,0 39,3 41,3 41,0 49,0 49,3 50,3 50,29 50,32 ; 0,32 8,32 8,37 16,37 16,32 24,32 24,37 32,37 32,32 50,32 ; 50,32 50,32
